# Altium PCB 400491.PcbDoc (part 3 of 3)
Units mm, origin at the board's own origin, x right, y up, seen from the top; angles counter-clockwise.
Board outline 85.6 x 53.98 mm, 4 copper layers (Top Layer, Mid-Layer 1, Mid-Layer 2, Bottom Layer), stack 1.528 mm thick; 280 components, 167 nets, 927 pads, 859 vias.
Unrouted connection lines stored in the file: 24.
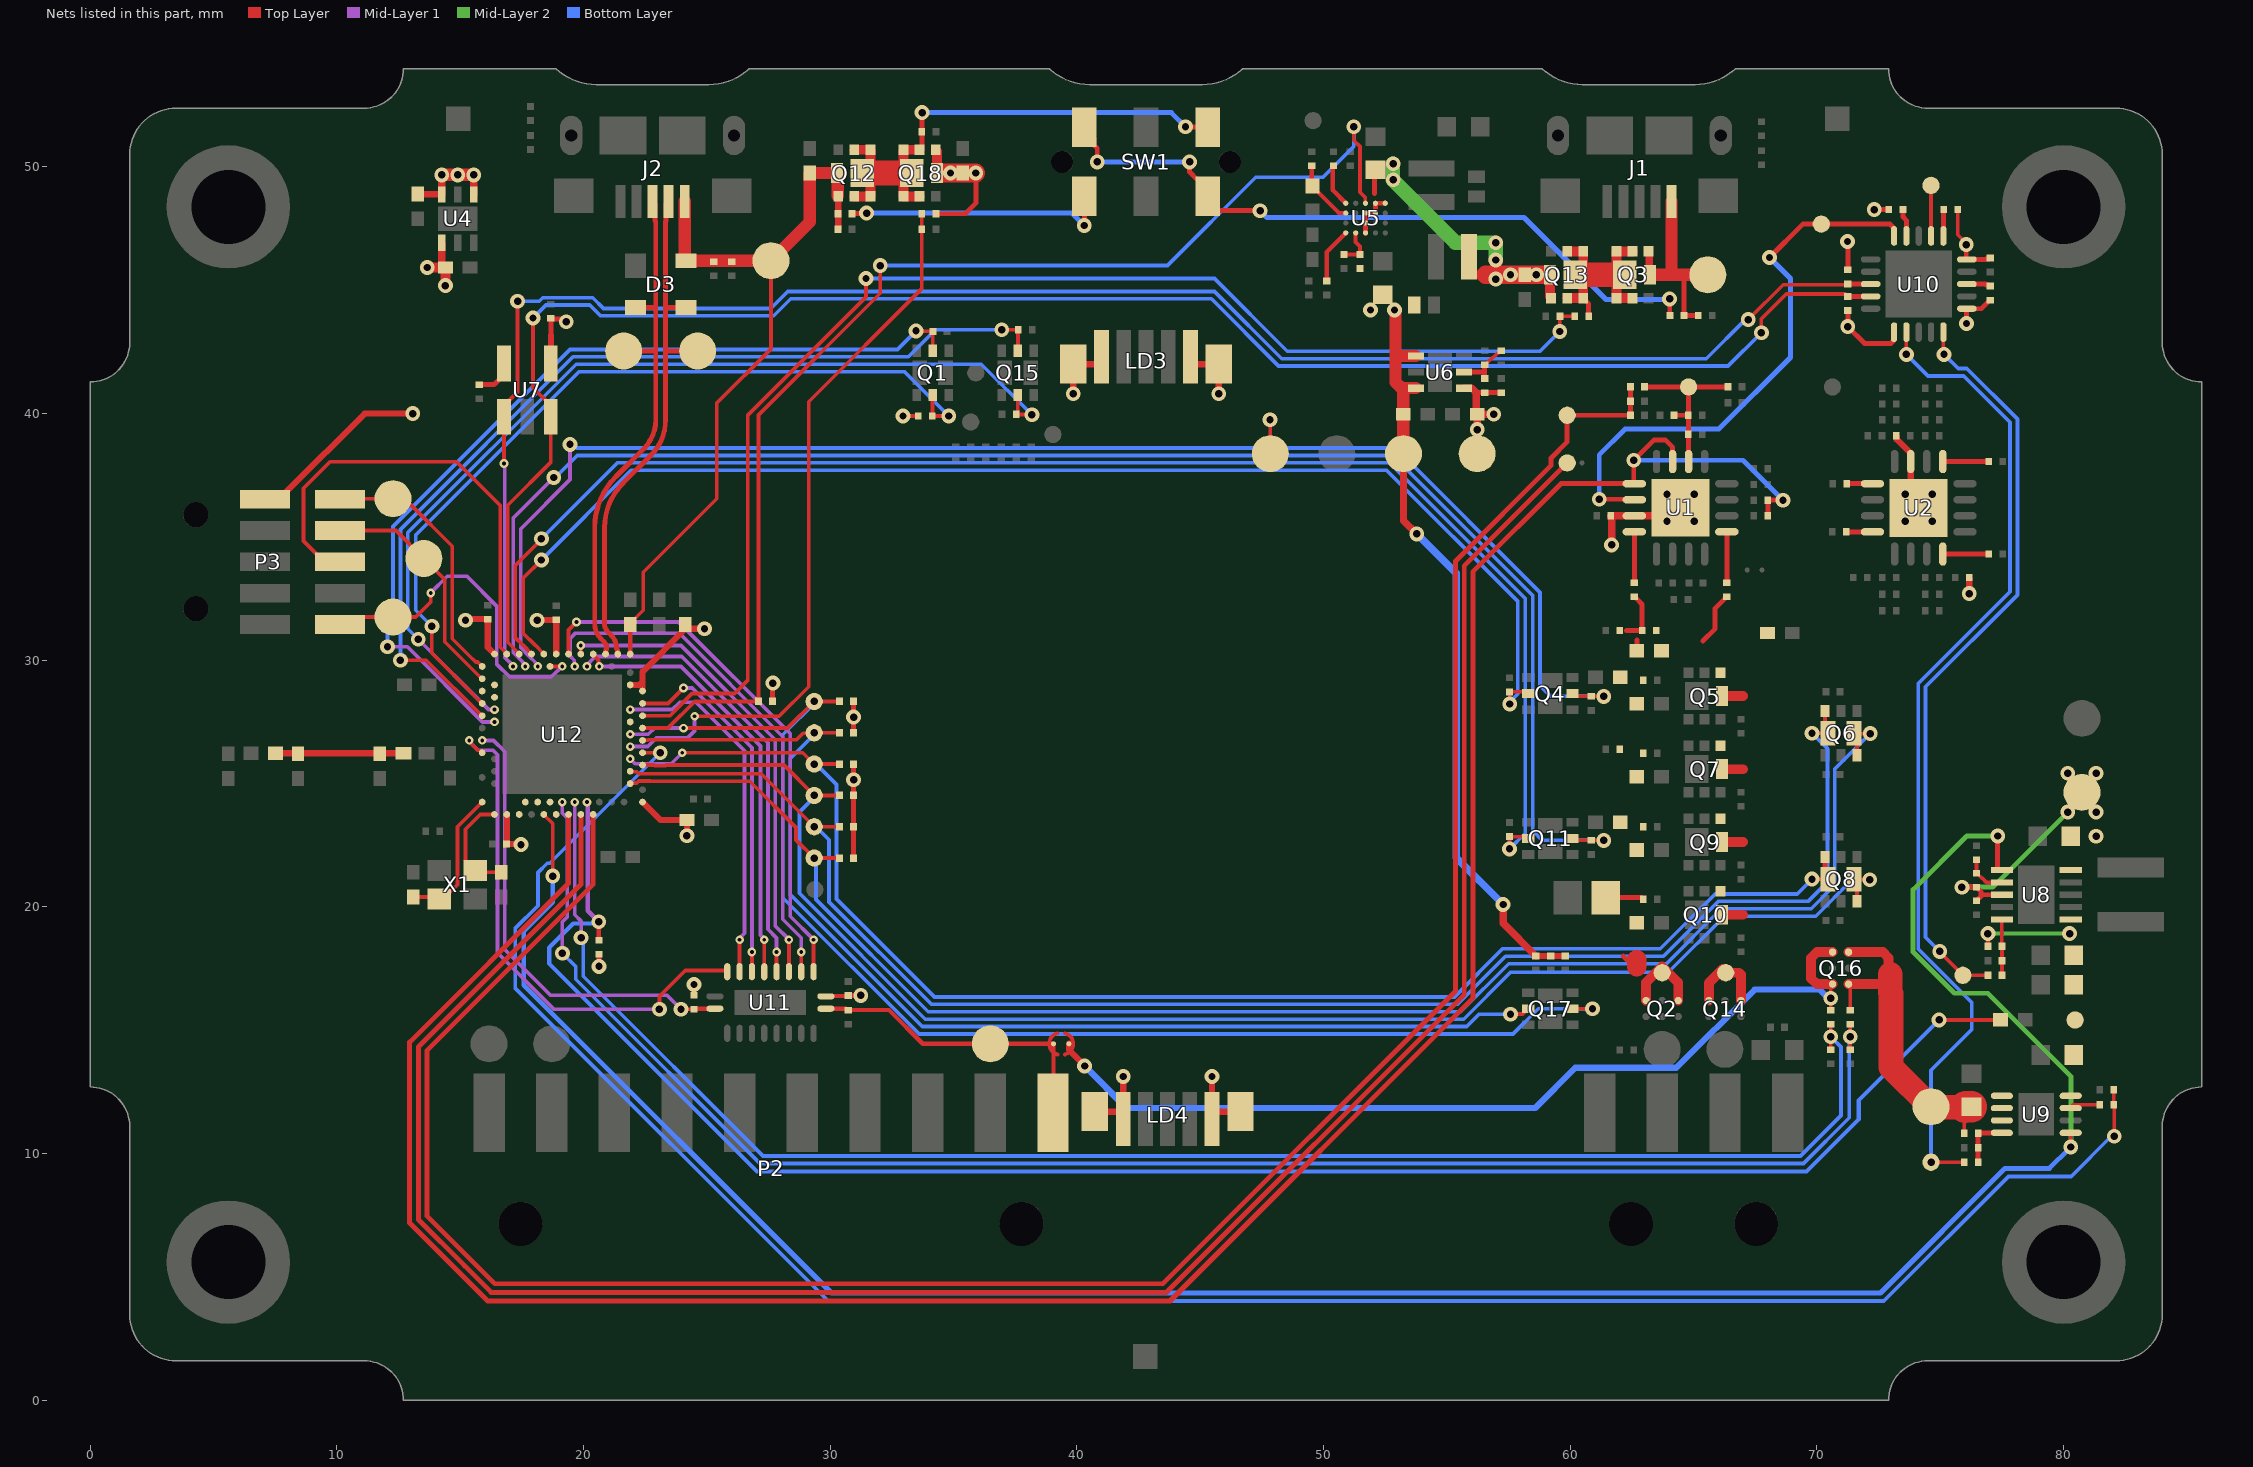
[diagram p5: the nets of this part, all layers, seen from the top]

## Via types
v1: diameter 0.6, hole 0.3, Top Layer to Bottom Layer, 767 vias
v2: diameter 0.35, hole 0.15, Top Layer to Mid-Layer 1, 92 vias

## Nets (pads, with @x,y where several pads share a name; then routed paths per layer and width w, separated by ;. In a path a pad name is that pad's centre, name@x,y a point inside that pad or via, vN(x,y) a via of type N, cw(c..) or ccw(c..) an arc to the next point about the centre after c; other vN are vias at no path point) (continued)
NetR11_2: R11.2 U2.1 | length 1.9
  Top Layer w0.2: U2.1@75.1,38.056 R11.2@76.965,38.056
NetR14_1: R14.1 R85.1 R87.2 U9.8 | length 2.1
  Top Layer w0.2: R14.1@76.535,9.65 R85.1@76.535,10.825 76.544,10.834 77.486,10.834 U9.8@77.495,10.844
NetR19_1: R19.1 U1.4 | length 2.1
  Top Layer w0.2: R19.1@62.596,33.146 U1.4@62.596,35.206
NetR20_2: R20.2 U2.5 | length 1
  Top Layer w0.2: R20.2@71.205,37.156 U2.5@72.25,37.156
NetR22_1: R22.1 U1.9 | length 2.1
  Top Layer w0.2: R22.1@66.346,33.146 U1.9@66.346,35.206
NetR25_2: R25.2 U2.8 | length 1.1
  Top Layer w0.2: R25.2@71.185,35.206 U2.8@72.25,35.206
NetR29_2: R29.2 U2.12 | length 2.2
  Top Layer w0.2: U2.12@75.1,33.954 U2.12@75.1,34.306 R29.2@76.965,34.306
NetR60_1: R60.1 SW1.6 | length 10.8
  Top Layer w0.2: R60.1@30.885,48.1 30.897,48.112 31.462,48.112 v1(31.475,48.125) ; v1(40.3,47.625) SW1.6@40.3,48.8
  Bottom Layer w0.2: v1(31.475,48.125) 39.8,48.125 v1(40.3,47.625)
NetR62_2: R62.2 SW1.3 SW1.4 | length 28.4
  Top Layer w0.2: SW1.3@40.3,51.6 40.7,51.2 40.7,50.873 40.825,50.748 v1(40.825,50.2) ; v1@44.525,50.2 44.566,50.159 44.566,49.793 44.859,49.5 44.9,49.5 45.25,49.15 45.25,48.75 45.213,48.713 45.7,48.225 v1(47.425,48.225) ; v1(64.025,44.65) 64.033,44.642 64.033,43.983 R62.2@64.04,43.975
  Bottom Layer w0.2: v1(40.825,50.2) v1(44.566,50.2) ; v1(47.425,48.225) 47.7,47.95 58.125,47.95 61.45,44.625 64,44.625 v1(64.025,44.65)
NetR71_2: R71.2 R77.1 R80.2 U6.2 | length 2.3
  Top Layer w0.15: R80.2@56.525,41.98 57.104,42.469 R71.2@57.2,42.55
  Top Layer w0.2: U6.2@55.696,41.684 56.509,41.684 ; R77.1@56.525,41.42 R80.2@56.525,41.98
NetR73_1: R73.1 R75.2 U5.D4 | length 1.7
  Top Layer w0.175: R75.2@50.825,46.45 R75.2@50.84,46.45 ; R75.2@50.888,46.498 R75.2@50.84,46.45 ; U5.D4@51.3,47.325 51.293,47.318 51.293,46.957 51.475,46.775 R73.1@51.475,46.45 51.46,46.45 R75.2@50.84,46.45
NetR74_2: R74.2 U5.E4 | length 2.3
  Top Layer w0.175: R74.2@50.125,45.375 50.125,46.55 U5.E4@50.9,47.325
NetR76_1: R76.1 R79.2 U5.E2 | length 2.6
  Top Layer w0.175: R79.2@49.525,50.04 49.525,49.225 50.618,48.132 50.893,48.132 U5.E2@50.9,48.125
NetR78_2: R78.2 U5.E1 | length 1.8
  Top Layer w0.175: R78.2@50.463,49.993 50.375,49.993 50.375,49.05 U5.E1@50.9,48.525
NetR83_2: R83.2 U7.5 | length 1.6
  Top Layer w0.2: R83.2@15.763,41.169 16.369,41.169 16.481,41.281 16.775,41.575 U7.5@16.775,42.025
NetR84_1: R84.1 R86.2 R112.1 U8.10 | length 2.3
  Top Layer w0.15: U8.10@77.495,19.494 77.495,18.414 R84.1@77.5,18.409 R86.2@77.5,17.819 R112.1@77.5,17.229
NetR88_1: R88.1 U10.13 | length 1
  Top Layer w0.2: U10.13@76.06,45.24 76.05,45.25 76.825,45.25 76.871,45.204 76.991,45.204 R88.1@77.026,45.169
NetR89_1: R89.1 U10.16 | length 1.1
  Top Layer w0.2: U10.16@75.125,47.175 75.132,47.183 75.132,48.266 R89.1@75.14,48.274
NetR114_1: R114.1 R115.2 U8.7 | length 1.7
  Top Layer w0.15: R114.1@76.465,21.369 76.48,21.369 76.69,21.159 76.708,21.159 76.873,20.994 U8.7@77.495,20.994 ; R114.1@76.465,21.369 R115.2@76.466,21.91
NetR116_1: R116.1 U10.19 | length 1.2
  Top Layer w0.2: R116.1@73.486,48.274 73.492,48.268 73.492,47.97 73.625,47.837 U10.19@73.625,47.175
P0.00_SW1_ONOFF: Q6.6 R43.1 TP30.1 U12.D2 | length 65.7
  Top Layer w0.145: U12.D2@21.89,25 21.914,25.024 22.162,25.024 22.243,25.105 22.708,25.105 22.716,25.098 22.8,25.098
  Top Layer w0.15: 22.8,25.098 26.732,25.098 28.614,23.215 28.614,22.716 v1(29.35,21.98) R43.1@30.375,21.98 ; Q6.6@71.36,26.919 71.625,26.727 Q6.6@71.625,26.138 ; Q6.6@71.45,27.043 71.536,27.129 71.536,27.168 71.61,27.205 71.639,27.091 71.656,27.025 v1(72.159,27.025)
  Bottom Layer w0.15: v1@29.425,21.98 29.425,20.301 33.976,15.75 55.552,15.75 57.502,17.7 63.899,17.7 66.124,19.925 69.766,19.925 70.725,20.884 70.725,25.591 v1(72.159,27.025)
P0.01_SW2_ONOFF: Q6.3 R47.1 TP31.1 U12.F2 | length 64.8
  Top Layer w0.145: U12.F2@21.89,25.5 21.914,25.476 22.162,25.476 22.243,25.395 22.745,25.395 22.75,25.4
  Top Layer w0.15: 22.75,25.4 27.2,25.4 v1(29.35,23.25) R47.1@30.375,23.25 ; v1(69.8,27.043) Q6.3@70.325,27.043 ; Q6.3@70.325,27.948 Q6.3@70.325,27.043 ; Q6.3@70.5,27.043 Q6.3@70.325,27.043
  Bottom Layer w0.15: v1@29.425,23.25 29.95,22.725 29.95,20.201 34.101,16.05 55.428,16.05 57.378,18 63.774,18 65.999,20.225 69.641,20.225 70.425,21.009 70.425,26.418 v1(69.8,27.043)
P0.02/AIN0_VREF_IA: C6.1 R10.1 U1.1 U1.15 U12.A12 | length 105.7
  Top Layer w0.2: U12.A12@19.39,23.75 19.39,20.955 12.95,14.515 12.95,7.185 15.035,5.1 15.985,4.15 16.11,4.025 43.775,4.025 56.05,16.3 56.05,33.581 59.625,37.156 U1.1@62.596,37.156 62.571,37.181 v1(62.571,38.106) 63.396,38.931 63.846,38.931 64.146,38.631 U1.15@64.146,38.056 ; C6.1@68.009,35.853 C6.1@68.006,35.856 R10.1@68.006,36.49 v1@68.769,36.49
  Bottom Layer w0.2: v1(62.571,38.106) 67.002,38.106 v1(68.622,36.486)
P0.03/AIN1_VLDO: R90.1 R92.2 U12.B13 | length 67.4
  Top Layer w0.15: R92.2@71.35,14.21 v1(71.35,14.737) R90.1@71.35,15.248
  Mid-Layer 1 w0.15: v1(19.14,18.125) 19.14,19.39 19.34,19.59 19.34,23.61 19.14,23.81 v2(19.14,24.25)
  Bottom Layer w0.15: v1(19.14,18.125) 19.684,17.581 19.684,17.258 19.684,17.067 27.151,9.6 27.342,9.6 69.458,9.6 71.309,11.451 71.309,14.697 v1(71.35,14.737)
P0.04/AIN2_VBB: R16.1 R91.2 U12.J1 | length 87.5
  Top Layer w0.15: U12.J1@22.39,26.25 v1(23.108,26.25) ; R91.2@82.03,12.593 R91.2@82.035,12.588 R16.1@82.035,11.975 82.05,11.96 v1(82.05,10.7)
  Bottom Layer w0.15: v1(23.108,26.25) 18.633,21.775 18.533,21.775 18.15,21.392 18.15,20.05 17.225,19.125 17.225,16.715 29.915,4.025 72.71,4.025 77.76,9.075 80.306,9.075 81.931,10.7 v1(82.05,10.7)
P0.05/AIN3_VIN: R110.1 R111.2 U12.K2 | length 29.7
  Top Layer w0.15: v2(24.5,27.725) 27.925,27.725 29.125,28.925 29.125,40.475 33.715,45.065 R111.2@33.715,47.475 R110.1@33.715,48.1
  Mid-Layer 1 w0.15: v2(21.89,26.5) 22.6,26.5 22.95,26.85 24.216,26.85 24.5,27.134 v2(24.5,27.725)
P0.06_VEXT_EN: Q17.2 R106.1 TP40.1 U12.L1 | length 47.3
  Top Layer w0.15: U12.L1@22.39,26.75 22.394,26.754 22.599,26.754 22.62,26.775 28.634,26.775 28.9,27.041 29.331,27.041 v1(29.35,27.06) R106.1@30.375,27.06 ; v1@57.775,15.66 58.07,15.66 Q17.2@58.285,15.875
  Bottom Layer w0.15: v1@29.425,27.06 28.378,26.013 28.378,20.5 33.728,15.15 55.801,15.15 56.301,15.65 v1(57.575,15.65)
P0.07_VLDO_EN: Q17.5 R107.1 TP41.1 U12.M2 | length 53.9
  Top Layer w0.15: v2(24.05,27.25) 28.27,27.25 v1(29.35,28.33) R107.1@30.375,28.33 ; Q17.5@60.095,15.875 v1(60.9,15.875)
  Mid-Layer 1 w0.15: v2(21.89,27) 22.625,27 22.875,27.25 v2(24.05,27.25)
  Bottom Layer w0.15: v1@29.425,28.33 28.078,26.983 28.078,20.376 33.604,14.85 57.675,14.85 58.7,15.875 v1(60.9,15.875)
P0.08_ANA_EN: R68.2 U5.C1 U12.N1 | length 50.2
  Top Layer w0.15: U12.N1@22.39,27.25 23.425,27.25 24.505,28.33 R68.2@27.09,28.33 27.09,39.941 32.025,44.876 v1(32.025,46) ; v1(51.225,51.625) 51.225,51.075 51.475,50.825 51.475,48.975 51.689,48.761 51.689,48.536 U5.C1@51.7,48.525
  Bottom Layer w0.15: v1(32.025,46) 43.675,46 47.25,49.575 49.975,49.575 51.225,50.825 v1(51.225,51.625)
P0.09_LP_EN: R102.1 U11.11 U12.L24 | length 18.7
  Top Layer w0.15: v1(23.95,15.85) 24.47,15.85 R102.1@24.475,15.855
  Top Layer w0.175: R102.1@24.475,15.855 24.495,15.875 U11.11@25.325,15.875
  Mid-Layer 1 w0.15: v2(15.89,26.75) 16.35,26.75 16.81,26.29 16.81,23.5 16.81,18.265 18.65,16.425 23.375,16.425 v1(23.95,15.85)
P0.10_LP_D0: U11.9 U12.J24 | length 21.4
  Top Layer w0.15: v2(15.365,26.75) 15.365,26.709 15.724,26.35 15.756,26.35 15.856,26.25 U12.J24@15.89,26.25 ; v1(23.075,15.85) 23.075,16.375 24.125,17.425 25.779,17.425 25.825,17.379 U11.9@25.825,17.375
  Mid-Layer 1 w0.15: v2(15.365,26.75) 15.365,26.709 15.724,26.35 16.326,26.35 16.51,26.166 16.51,23.5 16.51,18.141 18.801,15.85 v1(23.075,15.85)
P0.11_LP_D1: U11.8 U12.T2 | length 14.6
  Top Layer w0.15: U11.8@26.325,17.375 v2(26.325,18.675)
  Mid-Layer 1 w0.15: v2(21.89,28) 22.75,28 22.8,28 23.6,28 23.9,28.3 24.554,28.3 26.525,26.329 26.525,18.929 26.325,18.729 v2(26.325,18.675)
P0.12_LP_D2: U11.7 U12.U1 | length 14.8
  Top Layer w0.15: U12.U1@22.39,28.25 23.425,28.25 v2(24.05,28.875) ; U11.7@26.825,17.375 v2(26.825,18.175)
  Mid-Layer 1 w0.15: v2(24.05,28.875) 24.404,28.875 26.825,26.454 26.825,18.751 v2(26.825,18.175)
P0.13_LP_D3: U11.6 U12.AD8 | length 17.7
  Top Layer w0.15: U12.AD8@20.39,30.25 20.39,30.216 20.602,30.004 20.602,29.788 v2(20.64,29.75) ; v2@20.602,29.763 v2@20.64,29.725 ; U11.6@27.325,17.375 v2(27.325,18.675)
  Mid-Layer 1 w0.15: v2(20.64,29.75) 22.8,29.75 23.953,29.75 27.175,26.528 27.175,18.863 27.325,18.713 v2(27.325,18.675)
P0.14_LP_D4: U11.5 U12.AC9 | length 18.4
  Top Layer w0.15: U11.5@27.825,17.375 v2(27.825,18.175)
  Mid-Layer 1 w0.15: v2(20.14,29.75) 20.14,29.804 20.24,29.904 20.24,29.916 20.474,30.15 22.8,30.15 23.977,30.15 27.475,26.652 27.475,19.091 27.825,18.741 v2(27.825,18.175)
P0.15_LP_D5: U11.4 U12.AD10 | length 19.4
  Top Layer w0.15: U12.AD10@19.89,30.25 v2(19.89,30.6) ; U11.4@28.325,17.375 v2(28.325,18.675)
  Mid-Layer 1 w0.15: v2(19.89,30.6) 23.951,30.6 27.775,26.776 27.775,19.225 v2(28.325,18.675)
P0.16_LP_D6: U11.3 U12.AC11 | length 21.5
  Top Layer w0.15: U11.3@28.825,17.375 v2(28.825,18.175)
  Mid-Layer 1 w0.15: v2(19.64,29.75) 19.623,29.767 19.623,29.998 19.45,30.171 19.45,30.875 19.675,31.1 23.876,31.1 28.075,26.901 28.075,19.501 28.825,18.751 v2(28.825,18.175)
P0.17_LP_D7: U11.2 U12.AD12 | length 22
  Top Layer w0.15: U12.AD12@19.39,30.25 19.39,31.225 v2(19.715,31.55) ; U11.2@29.325,17.375 v2(29.325,18.675)
  Mid-Layer 1 w0.15: v2(19.715,31.55) 23.85,31.55 28.375,27.025 28.375,19.625 v2(29.325,18.675)
P0.20_CAL100K: Q4.2 R59.2 U12.AD16 | length 53.3
  Top Layer w0.15: v1(18.29,34.062) 17.55,33.323 17.55,31.096 18.033,30.613 18.04,30.613 18.39,30.263 U12.AD16@18.39,30.25 ; R59.2@57.535,28.715 R59.2@57.545,28.725 ; v1(57.545,28.225) R59.2@57.545,28.725 ; Q4.2@58.285,28.65 58.21,28.725 R59.2@57.545,28.725
  Bottom Layer w0.15: v1(18.29,34.062) 21.927,37.7 52.552,37.7 57.875,32.377 57.875,28.638 57.545,28.308 v1(57.545,28.225)
P0.21_CAL10K: Q4.5 R35.2 U12.AC17 | length 59.7
  Top Layer w0.15: Q4.5@60.095,28.65 Q4.5@60.127,28.617 ; Q4.5@60.127,28.535 R35.2@60.845,28.535 ; R35.2@60.856,28.535 v1(61.355,28.535)
  Mid-Layer 1 w0.15: v2(18.14,29.75) 18.14,29.804 18.04,29.904 18.04,29.916 17.806,30.15 17.45,30.506 17.45,35.325 19.45,37.325 v1(19.45,38.75)
  Bottom Layer w0.15: v1(19.45,38.75) 19.572,38.75 19.722,38.6 52.925,38.6 58.775,32.75 58.775,28.975 59.215,28.535 v1(61.355,28.535)
P0.22_CAL1K: Q11.2 R109.2 U12.AD18 | length 60.5
  Top Layer w0.15: U12.AD18@17.89,30.25 17.89,30.263 17.54,30.613 17.533,30.613 17.225,30.921 17.225,33.835 18.29,34.9 v1(18.29,34.925) ; R109.2@57.535,22.853 R109.2@57.538,22.85 ; v1(57.538,22.35) R109.2@57.538,22.85 ; Q11.2@58.285,22.775 58.21,22.85 R109.2@57.538,22.85
  Bottom Layer w0.15: v1(18.29,34.925) 21.365,38 52.676,38 58.175,32.501 58.175,22.988 v1(57.538,22.35)
P0.23_CAL100: Q11.5 R108.2 U12.AC19 | length 64.8
  Top Layer w0.15: Q11.5@60.095,22.775 60.173,22.697 R108.2@60.845,22.697 ; R108.2@60.856,22.697 v1(61.355,22.697)
  Mid-Layer 1 w0.15: v2(17.64,29.75) 17.64,29.804 17.54,29.904 17.54,29.916 17.15,30.306 17.15,35.767 v1(18.791,37.409)
  Bottom Layer w0.15: v1(18.791,37.409) 18.851,37.409 19.742,38.3 52.801,38.3 58.475,32.626 58.475,23.1 58.878,22.697 v1(61.355,22.697)
P0.26_SW3_ONOFF: Q8.6 R51.1 TP32.1 U12.G1 | length 62.2
  Top Layer w0.15: U12.G1@22.39,25.75 22.865,25.75 22.89,25.725 23.325,25.725 23.35,25.75 28.12,25.75 v1(29.35,24.52) R51.1@30.375,24.52 ; Q8.6@71.45,21.126 71.459,21.117 Q8.6@71.625,21.117 ; Q8.6@71.625,20.221 Q8.6@71.625,21.117 ; v1(72.137,21.099) 72.119,21.117 Q8.6@71.625,21.117
  Bottom Layer w0.15: v1@29.425,24.52 28.75,23.845 28.75,20.552 33.852,15.45 55.676,15.45 57.576,17.35 63.973,17.35 66.248,19.625 69.95,19.625 71.424,21.099 v1(72.137,21.099)
P0.27_SW4_ONOFF: Q8.3 R55.1 TP33.1 U12.H2 | length 59.6
  Top Layer w0.15: v2(24,26.25) 28.89,26.25 v1(29.35,25.79) R55.1@30.375,25.79 ; v1(69.8,21.126) 70.29,21.126 Q8.3@70.395,21.231
  Top Layer w0.2: Q8.3@70.325,22.031 70.325,21.231 70.395,21.231 Q8.3@70.5,21.126
  Mid-Layer 1 w0.15: v2(21.89,26) 22.09,25.8 23.55,25.8 v2(24,26.25)
  Bottom Layer w0.15: v1@29.425,25.79 30.25,24.965 30.25,20.325 34.225,16.35 55.304,16.35 57.254,18.3 63.65,18.3 65.875,20.525 69.199,20.525 v1(69.8,21.126)
P0.28/AIN4_VDUT: R34.1 R36.2 U12.B11 | length 66.3
  Top Layer w0.15: R36.2@70.556,14.21 v1(70.556,14.737) R34.1@70.556,15.248 R34.1@70.556,15.265
  Mid-Layer 1 w0.15: v2(19.64,24.25) 19.64,19.685 19.9,19.425 v1(19.9,18.75)
  Bottom Layer w0.15: v1(19.9,18.75) 19.984,18.666 19.984,17.191 27.275,9.9 69.334,9.9 70.975,11.541 70.975,14.318 v1(70.556,14.737)
P0.29/AIN5_AGND: SB2.1 TP10.1 U12.A10 | length 91.1
  Top Layer w0.2: U12.A10@19.89,23.75 19.89,20.91 13.3,14.32 13.3,7.33 15.18,5.45 16.13,4.5 16.255,4.375 43.63,4.375 55.7,16.445 55.7,33.825 TP10.1@59.875,38
P0.30/AIN6_NTC: R72.1 R113.2 U12.B9 | length 74.3
  Top Layer w0.175: v1(20.615,19.4) 20.62,19.395 20.62,18.655 R72.1@20.625,18.65 ; v1@74.95,15.35 v1(74.95,15.419) 74.95,15.438 74.969,15.419 R113.2@77.44,15.419
  Mid-Layer 1 w0.175: v2(20.14,24.25) 20.173,24.217 20.173,19.842 v1(20.615,19.4)
  Bottom Layer w0.175: v1(20.615,19.4) 20.539,19.324 19.579,19.324 18.603,18.348 18.603,17.706 27.034,9.275 69.575,9.275 71.687,11.387 71.687,12.156 v1(74.95,15.419)
P0.31/AIN7_VSE_IA: C8.2 R8.2 R9.2 TP1.1 U12.A8 | length 95.8
  Top Layer w0.2: U12.A8@20.39,23.75 20.39,20.915 13.65,14.175 13.65,7.475 16.4,4.725 43.485,4.725 55.35,16.59 55.35,34.025 59.225,37.9 59.225,38.2 59.875,38.85 TP1.1@59.875,39.931 ; TP1.1@59.875,39.897 60.097,39.897 60.131,39.931 C8.2@62.44,39.931 R9.2@62.44,40.506 R8.2@62.44,41.081
P1.01: U12.Y23
P1.02: U12.W24 | length 0
  Top Layer w0.15: U12.W24@15.877,28.75 U12.W24@15.89,28.75
P1.03: U12.V23
P1.04_VOUT_EN: Q1.2 R39.1 U12.U24 | length 34.6
  Top Layer w0.15: v1(13.85,31.375) 13.85,30.29 14.365,29.775 15.527,28.613 15.527,28.6 15.877,28.25 U12.U24@15.89,28.25 ; Q1.2@34.15,40.745 34.142,40.738 34.142,39.907 R39.1@34.135,39.9 v1(34.8,39.9)
  Bottom Layer w0.15: v1(13.85,31.375) 13.2,32.025 13.2,35.075 19.825,41.7 33,41.7 v1(34.8,39.9)
P1.05_LEDR: Q15.5 R99.2 U12.T23 | length 39.1
  Top Layer w0.15: R99.2@37.535,39.975 37.547,39.962 38.163,39.962 v1(38.175,39.95) ; R99.2@37.6,40.055 Q15.5@37.6,40.745
  Mid-Layer 1 w0.15: v1(13.3,30.85) 16.15,28 v2(16.39,28)
  Bottom Layer w0.15: v1(13.3,30.85) 12.875,31.275 12.875,35.174 19.701,42 36.125,42 v1(38.175,39.95)
P1.06_LEDG: Q15.2 R100.2 U12.R24 | length 38.8
  Top Layer w0.15: v1(12.575,30) 13.627,30 15.877,27.75 U12.R24@15.89,27.75 ; v1(36.95,43.4) R100.2@37.615,43.4 37.608,43.392 37.608,42.562 Q15.2@37.6,42.555
  Bottom Layer w0.15: v1(12.575,30) 12.575,35.299 19.576,42.3 33.167,42.3 34.267,43.4 v1(36.95,43.4)
P1.07_LEDB: Q1.5 R101.2 U12.P23 | length 36.6
  Top Layer w0.15: v1(33.475,43.35) 33.487,43.338 34.203,43.338 R101.2@34.215,43.325 ; Q1.5@34.15,42.555 34.158,42.562 34.158,43.318 R101.2@34.165,43.325
  Mid-Layer 1 w0.15: v1(12.05,30.55) 12.858,30.55 15.908,27.5 v2(16.39,27.5)
  Bottom Layer w0.15: v1(12.05,30.55) 12.05,31.1 12.275,31.325 12.275,35.423 19.452,42.6 32.725,42.6 v1(33.475,43.35)
P1.08: U12.P2
P1.09_EXT_USB: R17.2 R18.2 U12.R1 | length 54
  Top Layer w0.15: U12.R1@22.39,27.75 23.5,27.75 24.4,28.65 26.125,28.65 26.65,29.175 26.65,39.925 31.45,44.725 v1(31.45,45.475) ; v1(59.575,43.325) 59.577,43.327 59.577,43.948 R18.2@59.58,43.95 R17.2@60.175,43.95
  Bottom Layer w0.15: v1(31.45,45.475) 45.575,45.475 48.525,42.525 58.775,42.525 v1(59.575,43.325)
P1.10: U12.A20
P1.11: U12.B19
P1.12: U12.B17
P1.13: U8.6 U9.1 U12.A16 | length 98.2
  Top Layer w0.15: U12.A16@18.39,23.75 18.39,23.737 18.75,23.377 v1(18.75,21.25) ; U9.1@80.285,10.844 80.29,10.839 v1(80.29,10.269)
  Top Layer w0.2: U8.6@77.314,21.519 77.339,21.494 U8.6@77.375,21.494 ; v1(77.325,22.875) 77.325,21.544 U8.6@77.375,21.494 ; U8.6@77.495,21.494 U8.6@77.375,21.494
  Mid-Layer 2 w0.2: v1(77.325,22.875) 76.075,22.875 73.9,20.7 73.9,18.175 75.575,16.5 76.925,16.5 80.29,13.135 v1(80.29,10.269)
  Bottom Layer w0.2: v1(18.75,21.25) 18.75,20.19 17.575,19.015 17.575,16.825 30.05,4.35 72.575,4.35 77.625,9.4 79.421,9.4 v1@80.225,10.204
P1.14: U12.B15
P1.15: U12.A14
P3V3: C35.2 C46.1 C53.2 C54.1 C61.1 C62.1 C72.1 C73.1 C75.1 LD3.1 LD3.2 LD3.6 LD4.1 LD4.2 LD4.6 P3.1 R39.2 R43.2 R47.2 R51.2 R55.2 R68.1 R72.2 R81.2 R82.2 R88.2 R89.2 R102.2 R106.2 R107.2 R116.2 TP15.1 U4.1 U7.4 U10.6 U10.11 U10.15 U11.1 U12.A22 U12.AD14 U12.AD23 U12.B1 U12.W1 U12.Y2 | length 57.5
  Top Layer w0.15: v1(32.95,39.9) R39.2@33.565,39.9 ; v1(45.75,40.8) v1@45.803,40.747 ; v1(47.825,39.75) 47.838,39.75 TP15.1@47.838,38.375 ; R89.2@75.71,48.274 75.71,47.25 76.051,46.909 v1(76.051,46.849)
  Top Layer w0.175: U11.1@29.825,16.375 29.94,16.375 29.955,16.389 C54.1@30.707,16.389
  Top Layer w0.2: U4.1@14.247,46.925 U4.1@14.25,46.922 ; C35.2@14.25,46.072 C35.2@14.4,45.922 ; C46.1@18.675,43.865 C46.1@18.678,43.862 ; 18.681,43.181 18.678,43.184 C46.1@18.678,43.862 ; v1(19.3,43.725) 19.192,43.725 19.087,43.83 18.71,43.83 C46.1@18.678,43.862 ; v1(20.625,17.59) R72.2@20.625,18.08 ; R102.2@24.46,16.425 R102.2@24.475,16.425 v1(24.475,16.855) ; R68.1@27.66,28.33 27.66,29.06 v1(27.675,29.075) ; C54.1@30.725,16.407 v1@31.23,16.407 ; R43.2@30.945,21.98 R47.2@30.945,23.25 R51.2@30.945,24.52 R55.2@30.945,25.79 R55.2@30.95,25.795 ; R106.2@30.945,27.06 R107.2@30.945,28.33 ; R81.2@71.215,44.21 R81.2@71.25,44.175 v1(71.25,43.524) 71.925,42.849 73.001,42.849 73.125,42.972 U10.6@73.125,43.325 ; R82.2@71.25,45.825 v1@71.25,46.989 ; v1(72.325,48.268) 72.328,48.271 72.914,48.271 R116.2@72.916,48.274 ; U10.11@76.05,44.25 76.663,44.25 77.011,44.599 R88.2@77.026,44.599 ; v1(76.051,46.849) 76.051,46.251 76.825,46.251 76.847,46.274 76.991,46.274 C53.2@77.026,46.309 C53.2@77.011,46.309 ; v1(76.063,43.651) U10.11@76.063,44.249
  Top Layer w0.25: v1@15.215,31.675 16.065,31.675 16.115,31.625 16.115,30.525 U12.AD23@16.39,30.25 ; C62.1@16.89,22.525 C62.1@16.89,22.55 ; U12.A22@16.89,23.75 C62.1@16.89,22.55 ; v1@17.465,22.55 C62.1@16.89,22.55 ; v1(18.115,31.625) 18.89,31.625 U12.AD14@18.89,30.25 ; U12.Y2@21.89,29 22.265,29 22.39,29.125 ; U12.B1@22.39,24.25 23.115,23.525 C61.1@24.19,23.525 v1(24.19,22.888) ; U12.W1@22.39,28.75 22.39,29.125 ; v1@25.075,31.275 v1(24.9,31.275) 24.125,31.275 22.39,29.54 22.39,29.125
  Top Layer w0.254: P3.1@7.08,36.53 7.715,36.53 7.968,36.783 7.968,36.843 11.125,40 v1(13.075,40) ; U7.4@18.675,42.025 18.678,42.028 18.678,42.396 18.681,42.4 18.681,43.181 ; v1(39.85,40.8) LD3.1@39.85,42 40.827,42 41,42.173 LD3.2@41,42.223 ; LD4.1@40.725,11.7 41.702,11.7 LD4.6@41.875,11.527 ; LD4.6@41.875,11.4 LD4.6@41.875,11.527 ; v1@41.875,13.175 LD4.6@41.875,11.527 ; LD3.6@44.6,42.3 44.6,42.173 44.773,42 LD3.1@45.75,42 v1(45.75,40.8) ; LD4.2@45.475,11.4 LD4.2@45.475,11.527 ; v1@45.475,13.175 LD4.2@45.475,11.527 ; LD4.1@46.625,11.7 45.648,11.7 LD4.2@45.475,11.527
  Top Layer w0.3: C35.2@14.25,46.072 U4.1@14.25,46.922
  Top Layer w0.4: v1(13.666,45.922) C35.2@14.4,45.922 v1(14.4,45.188)
  other v1: 41.875,13.125 45.475,13.125 31.237,16.414 17.465,22.525 30.945,25.155 30.945,27.695 15.215,31.625 71.238,46.976
P7V0: C2.1 C9.2 C43.2 C45.2 R31.1 R77.2 TP17.1 U1.3 U1.17 U2.3 U2.17 U6.1 | length 12.9
  Top Layer w0.2: 56.194,40.85 C45.2@57.2,40.85
  Top Layer w0.25: C9.2@73.215,39.106 73.225,39.096 73.225,38.956 73.8,38.381 U2.3@73.8,38.056 73.8,36.506 U2.17@74.125,36.181 ; v1(76.17,32.7) R31.1@76.17,33.356
  Top Layer w0.3: U6.1@55.696,41.034 56.01,41.034 56.194,40.85 56.194,40.006 C43.2@56.225,39.975 v1(56.9,39.975) ; TP17.1@56.225,38.375 TP17.1@56.225,38.525 ; v1(56.225,39.35) TP17.1@56.225,38.525 ; C43.2@56.225,39.8 TP17.1@56.225,38.525 ; C2.1@61.641,35.856 61.675,35.822 v1(61.675,34.675) ; C2.1@61.771,35.856 U1.3@62.596,35.856 U1.17@64.146,35.856
  other v1: 63.921,35.631 65.021,35.631 73.575,35.631 74.675,35.631 63.921,36.731 65.021,36.731 73.575,36.731 74.675,36.731
P8V0: C38.2 C41.1 D4.1 R37.1 R73.2 R104.2 R105.2 TP16.1 U6.4 U6.6 | length 31.1
  Top Layer w0.254: R105.2@58.6,18.01 R104.2@59.2,18.01 R37.1@59.8,18.01
  Top Layer w0.3: TP16.1@53.238,38.513 TP16.1@53.238,38.375 53.238,35.658 v1(53.775,35.121) ; v1(57.275,20.1) 57.275,19.335 R105.2@58.6,18.01
  Top Layer w0.5: v1(52.875,44.2) 52.915,44.16 52.915,42.334 ; TP16.1@53.238,38.513 53.225,38.525 C41.1@53.225,39.975 53.225,41.034 ; U6.6@53.74,41.034 53.225,41.034 ; U6.4@53.74,42.334 52.915,42.334 ; 52.915,42.334 52.915,41.271 53.152,41.034 53.225,41.034
  Bottom Layer w0.3: v1(53.775,35.121) 55.375,33.521 55.375,22 v1(57.275,20.1)
  other v1: 51.9,44.2
POT0: R112.2 TP24.1 U10.10 | length 30.7
  Top Layer w0.15: v1(74.975,18.197) 74.975,18.169 TP24.1@75.915,17.229 R112.2@76.93,17.229 ; v1@75.125,42.399 U10.10@75.125,43.325
  Bottom Layer w0.15: v1(74.975,18.197) 74.4,18.772 74.4,28.925 78.125,32.65 78.125,39.775 76.075,41.825 75.724,41.825 v1(75.15,42.399)
POT1: R14.2 TP23.1 U10.7 | length 40.7
  Top Layer w0.15: v1(73.625,42.399) U10.7@73.625,43.325 ; v1(74.625,9.65) R14.2@75.965,9.65
  Bottom Layer w0.15: v1(73.625,42.399) 74.499,41.525 75.951,41.525 77.825,39.651 77.825,32.774 74.1,29.049 74.1,18.3 76.269,16.131 76.269,15.019 74.625,13.375 v1(74.625,9.65)
POT2: TP22.1 U10.17 | length 2.1
  Top Layer w0.15: U10.17@74.625,47.175 TP22.1@74.625,49.25
POT3: TP21.1 U1.2 U10.20 | length 23
  Top Layer w0.2: v1(61.175,36.525) 62.578,36.525 U1.2@62.596,36.506 ; v1(68.075,46.325) 69.429,47.679 TP21.1@70.175,47.679 72.958,47.679 73.125,47.511 U10.20@73.125,47.175
  Bottom Layer w0.2: v1(61.175,36.525) 61.175,38.325 62.225,39.375 66.025,39.375 68.925,42.275 68.925,45.475 v1(68.075,46.325)
RESET: P3.10 TP34.1 U12.AC13 U12.AC15 | length 13.8
  Top Layer w0.15: P3.10@10.13,31.447 10.433,31.75 TP34.1@12.275,31.75 13.2,31.75 13.8,32.35 v2(13.8,32.725) ; U12.AC15@18.64,29.75 v2(19.14,29.75)
  Mid-Layer 1 w0.15: v2(13.8,32.725) 14.475,33.4 15.275,33.4 16.475,32.2 16.475,29.849 16.995,29.33 18.705,29.33 19.125,29.75 v2(19.14,29.75)
RF: C66.2 C68.2 L4.2 R103.1 | length 5.1
  Top Layer w0.254: R103.1@7.515,26.229 C68.2@8.4,26.229 ; C68.2@8.425,26.229 C66.2@11.72,26.229 ; C66.2@11.735,26.229 L4.2@12.691,26.229
RFD_N: D3.3 J2.2 TP13.1 U12.AD4 | length 21.5
  Top Layer w0.2: U12.AD4@21.39,30.25 cw(c21.417,30.277) 21.379,30.277 21.379,30.386 ccw(c21.308,30.386) 21.358,30.437 cw(c21.408,30.487) 21.337,30.487 ccw(c20.584,30.487) 21.116,31.02 20.981,31.156 cw(c21.296,31.471) 20.85,31.471 20.85,35.373 cw(c23.39,35.373) 21.594,37.169 22.725,38.3 ccw(c21.281,39.744) 23.323,39.744 23.323,47.788 23.35,47.815 23.35,48.5 J2.2@23.45,48.6 ; 23.325,42.539 TP13.1@24.625,42.539 ; 23.335,44.297 D3.3@24.15,44.297
RFD_P: D3.2 J2.3 TP14.1 U12.AD6 | length 22.3
  Top Layer w0.2: U12.AD6@20.89,30.25 ccw(c20.863,30.277) 20.901,30.277 20.901,30.388 cw(c20.968,30.388) 20.921,30.435 ccw(c20.873,30.483) 20.94,30.483 ccw(c20.573,30.483) 20.833,30.742 20.699,30.876 cw(c21.291,31.469) 20.453,31.469 20.453,35.374 cw(c23.386,35.374) 21.312,37.449 22.444,38.581 ccw(c21.28,39.745) 22.926,39.745 22.926,44.228 22.926,44.297 ; TP14.1@21.625,42.539 22.925,42.539 ; D3.2@22.1,44.297 22.926,44.297 ; J2.3@22.8,48.6 22.891,48.509 22.891,47.823 22.926,47.788 22.926,45.247 ; 22.926,44.297 22.926,44.514 ; 22.927,44.514 22.927,45.247 ; 22.926,44.514 22.927,45.247
SCL: R82.1 U7.1 U10.3 U12.AC21 | length 73.9
  Top Layer w0.15: v2(16.775,37.975) U7.1@16.775,39.875 16.775,40.325 16.975,40.525 17.325,40.875 v1(17.325,44.55) ; v1(67.216,43.809) 68.633,45.225 71.225,45.225 71.25,45.25 U10.3@72.2,45.25
  Top Layer w0.2: R82.1@71.253,45.253 72.197,45.253 U10.3@72.2,45.25
  Mid-Layer 1 w0.15: v2(16.775,37.975) 16.8,37.95 16.8,30.125 17.14,29.785 v2(17.14,29.75)
  Bottom Layer w0.15: v1(17.325,44.55) 18.201,44.55 18.348,44.697 20.375,44.697 20.81,44.262 27.588,44.262 28.176,44.85 28.276,44.95 45.574,44.95 45.674,44.85 48.299,42.225 65.514,42.225 67.098,43.809 v1(67.216,43.809)
SDA: R81.1 U7.3 U10.4 U12.AD20 | length 73.4
  Top Layer w0.15: U12.AD20@17.39,30.25 17.39,30.263 16.925,30.728 16.925,36.285 18.675,38.035 U7.3@18.675,39.875 18.675,40.325 17.95,41.05 v1(17.95,43.875) ; v1(67.747,43.278) 67.747,43.847 68.75,44.85 71.15,44.85 71.25,44.75 U10.4@72.2,44.75
  Top Layer w0.2: R81.1@71.253,44.747 72.197,44.747 U10.4@72.2,44.75
  Bottom Layer w0.15: v1(17.95,43.875) 18.472,44.397 20.251,44.397 20.685,43.962 27.712,43.962 28.4,44.65 45.45,44.65 48.175,41.925 66.393,41.925 v1(67.747,43.278)
SE_OUT: C1.2 C4.2 R1.2 R4.1 R8.1 TP3.1 U1.14 | length 7
  Top Layer w0.2: R8.1@63.01,41.081 TP3.1@64.786,41.081 ; C4.2@64.206,39.931 C1.2@64.786,39.931 ; R1.2@64.786,39.156 C1.2@64.786,39.931 ; U1.14@64.796,38.056 R1.2@64.796,39.156 ; TP3.1@64.802,41.075 TP3.1@64.796,41.081 TP3.1@64.786,41.081 ; TP3.1@64.802,41.081 R4.1@66.39,41.081 ; C1.2@64.786,39.931 TP3.1@64.786,41.081
SWDCLK: P3.4 TP27.1 U12.AA24 | length 9.8
  Top Layer w0.15: P3.4@10.13,35.257 12.393,35.257 TP27.1@13.525,34.125 ; TP27.1@13.679,34.279 13.679,33.971 14.375,33.275 14.375,30.748 15.873,29.25 U12.AA24@15.89,29.25
SWDIO: P3.2 TP25.1 U12.AC24 | length 10.8
  Top Layer w0.15: P3.2@10.13,36.53 10.15,36.55 TP25.1@12.275,36.55 12.533,36.292 13.008,36.292 14.675,34.625 14.675,30.873 15.323,30.225 15.33,30.225 15.626,29.928 15.712,29.928 U12.AC24@15.89,29.75
SWO: P3.6 U12.AD22 | length 19.3
  Top Layer w0.15: P3.6@10.13,33.987 9.495,33.987 8.65,34.833 8.65,36.975 9.725,38.05 14.85,38.05 16.625,36.275 16.625,30.528 16.89,30.263 U12.AD22@16.89,30.25
VBB: C48.1 C49.1 C52.1 R16.2 R84.2 TP19.1 U8.1 U9.3 U9.4 | length 4.9
  Top Layer w0.15: R84.2@76.93,18.409 v1(76.93,18.919) ; 80.372,11.975 R16.2@81.458,11.975 ; C52.1@80.465,14.169 C52.1@80.472,14.162
  Mid-Layer 2 w0.15: v1(76.93,18.919) v1(80.24,18.919)
VBUS: Q12.3 Q18.3 R67.1 SW1.1 | length 21.3
  Top Layer w0.15: Q12.3@31.625,48.793 Q12.3@31.625,48.805
  Top Layer w0.2: Q18.3@33.625,50.695 33.715,50.785 R67.1@33.715,51.425 33.715,52.19 v1(33.725,52.2) ; v1(44.4,51.625) 45.175,51.625 45.3,51.75 SW1.1@45.3,51.9
  Top Layer w0.4: Q12.3@30.975,48.805 Q12.3@31.625,48.805 31.625,49.75 Q12.3@31.625,50.695 Q12.3@30.975,50.695 ; Q18.3@33.625,48.805 Q18.3@32.975,48.805 32.975,49.75 Q18.3@32.975,50.695 Q18.3@33.625,50.695
  Top Layer w1: Q12.3@31.625,49.75 Q18.3@32.975,49.75
  Bottom Layer w0.2: v1(33.725,52.2) 43.825,52.2 v1(44.4,51.625)
VBUS': C27.1 C28.1 C30.1 C74.1 D3.4 J2.1 Q12.2 R60.2 R64.1 TP9.1 U12.AD2 | length 31.7
  Top Layer w0.15: C74.1@21.89,31.5 22.415,32.025 22.415,33.565 25.4,36.55 25.4,40.425 27.597,42.622 TP9.1@27.597,46.197
  Top Layer w0.175: U12.AD2@21.89,30.25 C74.1@21.89,31.45
  Top Layer w0.254: R64.1@30.315,47.475 30.32,47.48 30.32,48.1 30.32,48.8 Q12.2@30.325,48.805
  Top Layer w0.5: J2.1@24.1,48.6 24.1,46.247 D3.4@24.15,46.197 25.275,46.197 26,46.197 TP9.1@27.597,46.197 29.175,47.775 C28.1@29.175,49.75 Q12.2@30.275,49.75 ; Q12.2@30.3,48.83 Q12.2@30.3,49.725
VBUSEXT: Q3.3 Q13.3 R17.1 | length 9.2
  Top Layer w0.2: Q13.3@60.525,44.68 60.525,44.668 60.745,44.448 R17.1@60.745,43.95
  Top Layer w0.4: Q13.3@59.875,44.68 Q13.3@60.525,44.68 60.525,45.625 Q13.3@60.525,46.57 Q13.3@59.875,46.57 ; Q3.3@62.525,44.68 Q3.3@61.875,44.68 61.875,45.625 Q3.3@61.875,46.57 Q3.3@62.525,46.57
  Top Layer w0.6: Q13.3@60.2,45.625 Q13.3@60.525,45.625 ; Q3.3@61.875,45.625 Q3.3@62.2,45.625
  Top Layer w1: Q13.3@60.525,45.625 Q3.3@61.875,45.625
VBUSEXT': J1.1 Q3.2 R61.1 R62.1 TP8.1 | length 9.4
  Top Layer w0.2: R61.1@65.19,43.975 R62.1@64.61,43.975 64.61,45.41 64.825,45.625 TP8.1@65.575,45.625
  Top Layer w0.3: Q3.2@63.175,46.57 63.2,46.545 63.2,45.65 Q3.2@63.225,45.625
  Top Layer w0.5: Q3.2@63.225,45.625 64.025,45.625 ; J1.1@64.1,48.6 64.1,45.7 64.025,45.625 ; TP8.1@65.575,45.625 64.825,45.625 64.61,45.625 64.025,45.625
VDD_EXT: C55.1 P2.10 SB3.2 TP11.1 U11.20 | length 12.7
  Top Layer w0.175: U11.20@29.825,15.875 30.653,15.875 30.71,15.818 C55.1@30.725,15.818 32.382,15.818 33.75,14.45 TP11.1@36.49,14.45 TP11.1@36.565,14.375 ; TP11.1@36.565,14.45 SB3.2@39.05,14.45 ; P2.10@38.625,12.055 P2.10@39.03,11.65 ; P2.10@39.05,12.055 SB3.2@39.05,14.375
VDUT+: C18.1 C20.1 Q5.2 Q7.2 Q9.2 Q10.2 Q14.1 Q14.3 Q16.1 Q16.3 R22.2 R34.2 R41.1 SB3.1 TP5.1 | length 47.2
  Top Layer w0.15: R34.2@70.556,15.835 v1(70.556,16.294) 70.556,16.753 70.631,16.828 Q16.3@70.631,16.869
  Top Layer w0.2: 65.371,30.781 65.87,31.28 65.87,32.1 66.296,32.526 66.296,32.541 66.331,32.576 R22.2@66.346,32.576 ; Q7.2@66.146,25.59 Q7.2@66.155,25.581
  Top Layer w0.254: 39.762,14.363 SB3.1@39.675,14.45 39.675,14.204 40.311,13.568 v1(40.311,13.55) v1@40.346,13.55
  Top Layer w0.4: Q14.3@65.616,16.206 65.616,16.926 66.185,17.495 TP5.1@66.3,17.495 ; Q10.2@66.146,19.681 66.996,19.681 ; Q9.2@66.146,22.631 66.996,22.631 ; Q5.2@66.146,28.548 66.996,28.548 ; Q7.2@66.155,25.581 67.005,25.581 ; TP5.1@66.3,17.331 66.846,17.331 66.916,17.261 Q14.1@66.916,16.206 ; Q16.3@70.631,16.869 69.996,16.869 69.762,17.103 69.762,17.934 69.996,18.169 Q16.1@70.631,18.169
  Bottom Layer w0.254: v1(40.311,13.55) 42.011,11.85 58.575,11.85 60.2,13.475 64.3,13.475 67.473,16.648 70.108,16.648 70.462,16.294 v1(70.556,16.294)
VDUT-: C19.2 C20.2 C21.2 C22.2 C23.2 C24.2 Q2.1 Q2.3 R19.2 R33.1 R38.2 R40.2 R41.2 R42.2 R46.2 R50.2 R54.1 R58.1 TP2.1 | length 7.8
  Top Layer w0.2: R38.2@61.44,20.375 62.907,20.375 62.961,20.321 C24.2@62.961,20.306 ; 62.146,18.006 62.296,17.856 ; 62.281,31.206 C20.2@62.846,31.206 ; R19.2@62.596,32.576 62.611,32.576 62.646,32.541 62.646,32.526 62.911,32.261 C20.2@62.911,31.206 ; R41.2@62.696,30.381 62.696,30.815
  Top Layer w0.4: 63.071,16.931 63.721,17.581 64.371,16.931 ; Q2.3@63.076,16.206 63.076,16.931 ; Q2.1@64.376,16.206 64.376,16.931
  Top Layer w0.8: 62.696,17.581 62.696,17.856
VIN: C3.1 C25.2 C26.2 C34.1 C39.1 C47.1 L1.1 Q13.2 Q18.2 R110.2 R114.2 TP12.1 U4.4 U4.6 U5.A1 U5.B1 U5.B2 U5.C2 U5.C3 U5.C4 U8.5 U8.8 | length 31.2
  Top Layer w0.2: R110.2@34.285,48.1 35.475,48.1 35.9,48.525 v1(35.9,49.75) ; U5.C4@51.7,47.325 U5.C3@51.7,47.725 U5.C2@51.7,48.125 U5.B2@52.1,48.125 U5.B1@52.1,48.525 52.493,48.525 U5.A1@52.497,48.528 ; C39.1@52.05,49.875 52.07,49.855 52.07,48.92 ; v1(75.874,20.799) R114.2@76.465,20.799 76.48,20.799 76.515,20.764 76.515,20.749 76.655,20.609 76.655,20.444 C3.1@76.465,20.254 ; 76.67,20.459 76.705,20.494 U8.8@77.495,20.494
  Top Layer w0.254: C34.1@13.27,48.905 C34.1@13.275,48.9 13.286,48.889 14.239,48.889 U4.6@14.25,48.878
  Top Layer w0.3: U4.6@14.25,48.878 v1(14.25,49.675) ; U4.4@15.55,48.878 v1(15.55,49.675)
  Top Layer w0.4: Q18.2@34.325,49.75 Q18.2@34.325,50.632 ; v1(56.975,46.225) 57.013,46.187 57.013,45.787 ; Q13.2@59.175,45.625 59.175,44.743 59.225,44.693 Q13.2@59.225,44.68
  Top Layer w0.5: v1(14.25,49.675) v1(14.9,49.675) v1(15.55,49.675)
  Top Layer w0.6: 57.013,45.787 57.175,45.625 v1@57.6,45.625 ; v1(58.625,45.625) 58.925,45.625
  Top Layer w0.762: 34.575,49.75 C26.2@35.375,49.75 v1(35.9,49.75) ; 56.575,45.625 57.6,45.625 Q13.2@59.025,45.625
  Mid-Layer 2 w0.2: v1(75.874,20.799) 77.12,20.799 v1(80.165,23.844)
  Mid-Layer 2 w0.6: v1@52.8,50.125 52.8,49.475 55.35,46.925 v1(56.975,46.925) v1(56.975,46.225)
  other v1: 81.315,22.869 81.315,23.844 80.165,25.419 81.315,25.419 56.975,45.45 57.575,45.625 52.825,49.475 34.875,49.75 52.825,50.125
VLDO: C50.1 Q16.4 Q16.6 R85.2 R90.2 TP20.1 U9.5 U9.6 U9.7 | length 14.3
  Top Layer w0.15: R90.2@71.35,15.835 Q16.4@71.35,16.759 ; R85.2@75.965,10.825 75.965,11.594 C50.1@76.265,11.894
  Top Layer w0.175: U9.7@77.481,11.329 U9.7@77.495,11.344
  Top Layer w0.4: Q16.4@71.281,16.869 72.671,16.869 ; Q16.6@71.281,18.169 72.671,18.169 72.906,17.934 72.906,16.603
  Top Layer w1: 72.975,17.26 72.975,16.519 73,16.494 73,13.5 74.625,11.875 C50.1@76.002,11.875
  Top Layer w1.27: C50.1@76.002,11.875 76.02,11.894 C50.1@76.265,11.894
XC1: C59.1 U12.B24 X1.1 | length 5.8
  Top Layer w0.15: C59.1@13.101,20.405 14.395,20.405 14.89,20.9 14.89,23.25 U12.B24@15.89,24.25
XC2: C57.1 U12.A23 X1.3 | length 4.3
  Top Layer w0.15: U12.A23@16.39,23.75 15.815,23.75 15.215,23.15 15.215,21.868 X1.3@15.604,21.48 15.679,21.405 C57.1@16.657,21.405
pads on no net: Fid1.0 Fid2.0 Fid3.0 J1.2 J1.3 J1.4 J1.6@59.5,51.275 J1.6@66.1,51.275 J2.4 J2.6@19.5,51.275 J2.6@26.1,51.275 P1.0 P2.0 P3.0 P3.7 P3.8 SW1.0 U1.13 U1.16 U2.13 U2.16 U4.2 U4.5 U5.D3 U6.5 U10.12 U11.21 U12. U12.A18 U12.AB2 U12.B3

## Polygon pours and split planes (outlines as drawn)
GND on Mid-Layer 1 "Mid-Layer 1-GND" (solid, remove dead copper, pour order 37): 85.6,53.98 0,53.98 0,18.4 0,0 85.6,0
AGND on Mid-Layer 1 "Mid-Layer 1-AGND" (solid, pour order 26): 60.1,33.3 61.889,31.511 67.136,31.511 67.475,31.85 67.475,33.925 69.4,35.85 69.4,41.325 68.592,42.133 61.983,42.133 60.1,40.25
P3V3 on Mid-Layer 2 "Mid-Layer 2-P3V3" (solid, remove dead copper, pour order 43): 9.95,10.1 9.95,49.45 80.125,49.45 80.125,10.1
GND on Mid-Layer 2 "Mid-Layer 2-GND" (solid, pour order 42): 0,0 0,53.98 11.1,53.98 11.1,24.875 23.575,12.4 46.675,12.4 47.5,13.225 47.5,36.1 85.6,36.1 85.6,0
P7V0 on Mid-Layer 2 "Mid-Layer 2-P7V0" (solid, pour order 33): 56.65,32.382 55.55,33.482 55.55,39.482 56.425,40.357 58.9,40.357 78.15,40.357 78.15,32.382
VIN on Mid-Layer 2 "Mid-Layer 2-VIN" (solid, pour order 38): 11.1,53.98 85.6,53.98 85.6,22.225 79.35,22.225 78.45,23.125 78.45,45.275 74.95,48.775 70.895,48.775 67.258,45.138 55.012,45.137 51.775,48.375 11.1,48.375
GND on Top Layer "Top_Layer-GND" (solid, remove dead copper, pour order 41): 0,0 0,53.98 85.6,53.98 85.6,0
AGND on Top Layer "Top Layer-AGND" (solid, remove dead copper, pour order 36): 60.1,33.325 62.044,31.381 67.021,31.381 67.725,32.085 67.725,34.175 69.4,35.85 69.4,41.325 68.769,41.956 61.681,41.956 60.1,40.375
VDUT- on Top Layer "Top_Layer-VDUT-" (solid, pour order 35): 61.965,17.425 62.89,16.5 64.59,16.5 64.59,19.54 61.965,19.54
VDUT+ on Top Layer "Top_Layer-VDUT+" (solid, remove dead copper, pour order 18): 66.146,19.681 66.146,29.451 65.516,30.081 63.371,30.081 63.371,31.356 68.121,31.356 68.5,30.977 68.5,17.1 67.9,16.5 65.415,16.5 65.415,18.2 66.146,18.2
EXT_POWER_IN on Top Layer "Top_Layer-EXT_POWER_IN" (solid, pour order 40): 65.616,10.05 66.916,10.05 66.916,15.556 65.616,15.556
EXT_POWER_OUT on Top Layer "Top_Layer-EXT_POWER_OUT" (solid, pour order 39): 63.076,10.05 64.376,10.05 64.376,15.575 63.076,15.575
GND on Bottom Layer "Bottom_Layer-GND" (solid, remove dead copper, pour order 8): 0,0 0,53.98 85.6,53.98 85.6,0

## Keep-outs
Keep-Out Layer:
  circle w0.15: c80,48.38 r3
  circle w0.15: c5.6,48.38 r3
  circle w0.15: c5.6,5.6 r3
  circle w0.15: c80,5.6 r3
  region: 33.805,36.555 ccw(c33.805,34.485) 31.735,34.485 31.735,19.485 ccw(c33.805,19.485) 33.805,17.415 51.805,17.415 ccw(c51.805,19.485) 53.875,19.485 53.875,34.485 ccw(c51.805,34.485) 51.805,36.555
  lines w0.15: 31.735,19.485 ccw(c33.805,19.485) 33.805,17.415 51.805,17.415 ccw(c51.805,19.485) 53.875,19.485 53.875,34.485 ccw(c51.805,34.485) 51.805,36.555 33.805,36.555 ccw(c33.805,34.485) 31.735,34.485 31.735,19.485

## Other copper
Top Layer:
  region net NetC21_1: 63.396,29.493 63.396,27.603 65.121,27.603 65.121,29.493
  region net NetC24_1: 63.396,20.626 63.396,18.736 65.121,18.736 65.121,20.626
  region net NetC23_1: 63.396,23.576 63.396,21.686 65.121,21.686 65.121,23.576
  region net NetC22_1: 63.396,26.535 63.396,24.645 65.121,24.645 65.121,26.535
  pour cut-out: 0,12.7 5.156,12.7 5.156,28.75 0,28.75
  region net GND: 54.225,42.875 54.225,39.35 55.2,39.35 55.2,42.875
  region net VLDO: 72.475,18.35 73.5,18.35 73.5,16.369 72.475,16.369
  region net VDUT+: 70.295,18.175 70.295,16.875 69.35,16.875 68.22,16.875 68.22,18.175
  region: 63.396,27.381
  region net NetD5_1: 52.5,48.025 57.2,48.025 57.2,49.05 53.425,49.05 52.5,48.125
  region net NetD4_2: 52.375,47.825 53.6,47.825 54.15,47.275 55.125,47.275 55.125,43.9 54.225,43.9 54.225,46.4 53,47.625 52.375,47.625
  region net P8V0: 51.325,45.88 51.325,43.15 53.925,43.15 53.925,45.3 52.075,45.3 51.495,45.88
  region net GND: 52.1,47.35 52,47.25 52,45.7 53.425,45.7 53.425,46.8 52.875,47.35
  region net NetC40_2: 49.275,47.25 50.175,47.25 50.65,47.725 50.45,47.725 49.975,48.2 49.275,48.2
  region net VIN: 52.1,48.125 53.15,49.175 53.15,50.45 51.7,50.45 51.7,49.075 52.025,48.75 52.025,48.125
  region net NetL3_1: 80.641,20.869 79.84,20.869 79.84,21.119 80.765,21.119 81.265,21.619 81.265,22.044 84.14,22.044 84.14,20.869
  pour cut-out: 81.036,18.744 81.036,22.344 84.365,22.344 84.365,18.744
  region net VIN: 79.84,21.369 80.74,21.369 81.04,21.669 81.04,22.344 81.64,22.344 81.64,25.75 79.84,25.75
  region net NetL3_2: 80.641,20.119 79.84,20.119 79.84,19.869 80.765,19.869 81.265,19.369 81.265,18.944 84.14,18.944 84.14,20.119
  region net VIN: 55.575,45.05 55.575,47.275 57.375,47.275 57.375,45.05
  region net VLDO: 77.94,12.519 77.94,11.219 76.995,11.219 75.865,11.219 75.865,12.519
  pour cut-out: 15.808,27.325 13.065,27.325 13.065,25.475 13.865,25.475 13.865,24.429 15.808,24.429
  pour cut-out: 57.45,48.025 54.191,48.025 54.191,47.275 57.45,47.275
  pour cut-out: 16.567,30.987 17.627,29.927 15.86,28.159 14.799,29.22
  region net GND: 68.4,31.6 68.4,34.518 67.634,34.518 67.634,31.6
  region net N2V0: 49.225,50.475 49.225,52.2 49.9,52.2 49.9,50.475
  pour cut-out: 18.89,27.75 18.89,26.25 16.39,26.25 16.39,27.75
  region net VDUT-: 61.875,17.515 62.777,16.613 63.721,17.575 63.721,18.211 63.1,18.211 63.1,31.381 61.875,31.381
  region net VBB: 79.84,19.625 80.725,19.625 81.04,19.31 81.04,16.844 81.04,11.7 79.84,11.7
  region net N2V0: 55.775,49.35 55.775,52.275 57.2,52.275 57.2,49.35
  region net GND: 79.64,24.15 79.64,8.15 78.14,8.15 78.14,24.15
  region net GND: 55.516,49.375 55.516,52.275 51.7,52.275 51.7,50.75 53.375,50.75 53.375,49.375
Mid-Layer 1:
  pour cut-out: 0,12.7 5.156,12.7 5.156,28.75 0,28.75
Mid-Layer 2:
  pour cut-out: 0,12.7 5.156,12.7 5.156,28.75 0,28.75
Bottom Layer:
  pour cut-out: 0,12.7 5.156,12.7 5.156,28.75 0,28.75

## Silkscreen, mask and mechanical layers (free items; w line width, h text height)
Top Overlay:
  drawing of 912 lines, arcs and shapes, not listed
  text "OFF" at 35.767,52.675 h1.7
  text "ON" at 47.494,52.675 h1.7
  text "J2" at 27.35,52.575 h1
  text "J1" at 56.8,52.575 h1
  text "GND" at 8.175,46.9 h1
  text "SW1" at 41.654,46.593 h1
  text "GND" at 78.517,44.6 h1
  text "P3" at 3.425,29.4 h1
  text "P2" at 12.8,6.65 h1
  text "P1" at 58.175,6.65 h1
  text "GND" at 74.6,6.25 h1
  text "GND" at 8.024,6.213 h1
  text "'.PCBNumber'" at 48.45,1.494 h2.03
  text "'.PCBRevision'" at 48.399,0.524 h0.67
  text "GND" at 60.57,0.46 h1 r90
  text "D0" at 15.64,0.395 h0.67 r90
  text "D1" at 18.18,0.395 h0.67 r90
  text "D2" at 20.72,0.395 h0.67 r90
  text "D3" at 23.26,0.395 h0.67 r90
  text "D4" at 25.8,0.395 h0.67 r90
  text "D5" at 28.34,0.395 h0.67 r90
  text "D6" at 30.88,0.395 h0.67 r90
  text "D7" at 33.42,0.395 h0.67 r90
  text "GND" at 35.96,0.395 h0.67 r90
  text "VCC" at 38.5,0.395 h0.67 r90
  text "OUT" at 63.31,0.26 h1 r90
  text "IN" at 65.85,0.26 h1 r90
  text "GND" at 68.39,0.26 h1 r90
Bottom Overlay:
  drawing of 82 lines, arcs and shapes, not listed
  text "OFF" at 40.626,50.965 h1.78
  text "ON" at 46.85,50.965 h1.78
  text "USB" at 24.225,50.886 h2.03
  text "USB" at 64.225,50.886 h2.03
  text "DATA/POWER" at 27.696,48.922 h2.03
  text "POWER ONLY" at 67.699,48.922 h2.03
  text "POWER" at 45.473,48.901 h2.03
  text "Power Profiler Kit II" at 75.25,39.775 h9.25
  text "MAX 1A" at 67.475,35.75 h2.03
  text "A" at 66.081,30.984 h5
  text "SMU" at 74.8,24.805 h2.03
  text "Getting started: / nordicsemi.com/startppk2" at 31.375,24.35 h3
  text "AMP" at 70.447,20.225 h2.03
  text "0.8V - 5.0V" at 76.55,19.6 h2.03 r270
  text "VIN MAX 5.0V" at 64.35,11.4 h2.03 r270
  text "LOGIC PORT" at 32.308,5.05 h2.03
  text "D0" at 15.532,0.38 h2.03 r270
  text "D1" at 18.075,0.38 h2.03 r270
  text "D2" at 20.615,0.38 h2.03 r270
  text "D3" at 23.155,0.38 h2.03 r270
  text "D4" at 25.695,0.38 h2.03 r270
  text "D5" at 28.235,0.38 h2.03 r270
  text "D6" at 30.775,0.38 h2.03 r270
  text "D7" at 33.315,0.38 h2.03 r270
  text "GND" at 35.855,0.38 h2.03 r270
  text "VCC" at 38.395,0.38 h2.03 r270
  text "GND" at 60.51,0.38 h2.03 r270
  text "VOUT" at 63.05,0.38 h2.03 r270
  text "VIN" at 65.59,0.38 h2.03 r270
  text "GND" at 68.13,0.38 h2.03 r270
Board Outline:
  lines w0.15: 18.881,53.98 12.7,53.98 cw(c11.1,53.98) 11.1,52.38 3.48,52.38 ccw(c3.48,50.5) 1.6,50.5 1.6,42.88 cw(c0,42.88) 0,41.28 0,12.7 cw(c0,11.1) 1.6,11.1 1.6,3.48 ccw(c3.48,3.48) 3.48,1.6 11.1,1.6 cw(c11.1,0) 12.7,0 72.9,0 cw(c74.5,0) 74.5,1.6 82.12,1.6 ccw(c82.12,3.48) 84,3.48 84,11.1 cw(c85.6,11.1) 85.6,12.7 85.6,41.28 cw(c85.6,42.88) 84,42.88 84,50.5 ccw(c82.12,50.5) 82.12,52.38 74.5,52.38 cw(c74.5,53.98) 72.9,53.98 66.694,53.98 ; 18.881,53.98 ccw(c20.518,55.736) 20.518,53.336 25.082,53.336 ccw(c25.082,55.736) 26.719,53.98 38.881,53.98 ; 38.881,53.98 ccw(c40.518,55.735) 40.518,53.335 45.082,53.335 ccw(c45.082,55.735) 46.719,53.98 ; 46.719,53.98 58.856,53.98 ; 58.856,53.98 ccw(c60.493,55.736) 60.493,53.336 65.057,53.336 ccw(c65.057,55.736) 66.694,53.98 ; 33.2,19.47 ccw(c34.78,19.47) 34.78,17.89 50.82,17.89 ccw(c50.82,19.47) 52.4,19.47 52.4,34.51 ccw(c50.82,34.51) 50.82,36.09 34.78,36.09 ccw(c34.78,34.51) 33.2,34.51 33.2,19.47
Dimensions:
  circle w0.254: c5.6,5.6 r1.5
  circle w0.254: c5.6,48.38 r1.5
  circle w0.254: c80,48.38 r1.5
  circle w0.254: c80,5.6 r1.5
Top Assembly:
  drawing of 48 lines, arcs and shapes, not listed
  text "LABEL" at 51.15,8.85 h1.02
Top Impedance Info:
  lines w0.145: 15.591,25.997 15.693,25.895 16.275,25.895 16.38,26 16.415,26
  lines w0.15: 15.03,26.229 cw(c15.03,25.436) 15.591,25.997
  lines w0.2: 21.39,30.25 cw(c21.417,30.277) 21.379,30.277 21.379,30.386 ccw(c21.308,30.386) 21.358,30.437 cw(c21.408,30.487) 21.337,30.487 ccw(c20.584,30.487) 21.116,31.02 20.981,31.156 cw(c21.296,31.471) 20.85,31.471 20.85,35.373 cw(c23.39,35.373) 21.594,37.169 22.725,38.3 ccw(c21.281,39.744) 23.323,39.744 23.323,47.788 23.35,47.815 23.35,48.5 23.45,48.6 ; 21.625,42.539 22.925,42.539 ; 22.1,44.297 22.926,44.297 ; 22.8,48.6 22.891,48.509 22.891,47.823 22.926,47.788 22.926,45.247 ; 22.929,44.297 22.926,44.297 ; 23.325,42.539 24.625,42.539 ; 23.335,44.297 24.15,44.297 ; 20.89,30.25 ccw(c20.863,30.277) 20.901,30.277 20.901,30.388 cw(c20.968,30.388) 20.921,30.435 ; 20.89,30.25 20.89,30.25 ; 20.921,30.435 ccw(c20.873,30.483) 20.94,30.483 ccw(c20.573,30.483) 20.833,30.742 20.699,30.876 cw(c21.291,31.469) 20.453,31.469 20.453,35.374 cw(c23.386,35.374) 21.312,37.449 22.444,38.581 ; 20.921,30.435 20.921,30.435 ; 20.921,30.435 20.921,30.435 ; 22.444,38.581 ccw(c21.28,39.745) 22.926,39.745 22.926,44.228 22.926,44.297 ; 22.444,38.581 22.444,38.581 ; 22.926,44.297 22.926,44.514 ; 22.927,44.514 22.927,45.247 ; 22.926,44.514 22.927,45.247
  lines w0.22: 13.716,26.229 15.03,26.229
  lines w0.254: 7.54,26.229 8.425,26.229 ; 8.45,26.229 11.745,26.229 ; 11.76,26.229 12.716,26.229
  text "Top layer signals: / 90 ohm differential / 45 ohm single ended" at 20.25,33.4 h1.5 r90
  text "Top layer signals: / 50 ohm single ended" at 5.7,26.725 h1.5

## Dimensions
80,5.6 to 82.498,3.102 on Dimensions
74.5,0 to 75.1,1.05 on Dimensions
80,48.38 to 80,5.6 on Dimensions
0,41.28 to 0,12.7 on Dimensions
82.12,3.48 to 88.189,-2.589 on Dimensions
5.6,5.6 to 80,5.6 on Dimensions
12.7,53.98 to 72.9,53.98 on Dimensions
12.7,53.98 to 12.7,0 on Dimensions
34.78,34.51 to 30.896,38.394 on Dimensions
1.6,42.88 to 84,50.5 on Dimensions
3.48,52.38 to 3.48,1.6 on Dimensions
52.4,19.47 to 33.2,19.47 on Dimensions
50.82,36.09 to 50.82,17.89 on Dimensions
50.82,17.89 to 72.9,0 on Dimensions
72.9,53.98 to 50.82,36.09 on Dimensions
52.4,19.47 to 85.6,12.7 on Dimensions
0,12.7 to 33.2,19.47 on Dimensions
0,35.1 to 85.6,41.28 on Dimensions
